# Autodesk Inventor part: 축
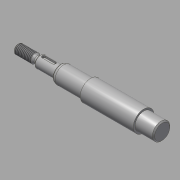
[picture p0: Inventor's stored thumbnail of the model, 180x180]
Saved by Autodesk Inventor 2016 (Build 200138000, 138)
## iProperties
Created: 2015-11
Part Number: 축
Material: 강철, 연강
Document SubType Name: Modeling
Designer: mduedu
Density: 1 g/cm^3
Appearance: 강철
Author: mduedu
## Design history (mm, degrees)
sketch "스케치1"
  geometry: L1 (-86, 0)-(86, 0); L2 (-86, 0)-(-86, 4); L3 (-86, 4)-(-70.732, 4); L4 (-70.732, 4)-(-69, 3); L5 (-69, 3)-(-67, 3); L6 (-67, 3)-(-67, 5); L7 (-67, 5)-(-49, 5); L8 (-49, 5)-(-49, 6.55); L9 (-47.355, 7.5)-(-23, 7.5); L10 (-23, 7.5)-(-23, 9); L11 (0, 0)-(0, 9); L12 (86, 4)-(70.732, 4); L13 (70.732, 4)-(69, 3); L14 (69, 3)-(67, 3); L15 (67, 3)-(67, 5); L16 (67, 5)-(49, 5); L17 (23, 7.5)-(23, 9); L18 (86, 0)-(86, 4); L19 (-23, 9)-(23, 9); L20 (-49, 6.55)-(-47.355, 7.5); L21 (47.355, 7.5)-(23, 7.5); L22 (49, 6.55)-(47.355, 7.5); L23 (49, 5)-(49, 6.55); 1 further point
  constraints: 46 end point, 10 symmetric about line, 6 perpendicular, 5 parallel, 2 midpoint, 1 coincident, 1 horizontal
  dimensions: "d0" = 172 distance of L1.start L1.end (derived); "d1" = 8 diameter of L3 L1; "d2" = 30 deg angle of L4 L5; "d3" = 6 diameter of L5 L1; "d4" = 10 diameter of L7 L1; "d5" = 15 diameter of L9 L1; "d6" = 18 diameter of L19 L1; "d8" = 18 distance of L6.end L7.end; "d9" = 46 distance of L10.end L17.end; "d10" = 2 distance of L4.end L5.end; "d11" = 17 distance from line of L4.end L2; "d16" = 13.1 diameter of L8.end L1; "d17" = 30 deg angle of L20 L9; "d18" = 26 distance between parallel lines of L10 L8
revolve "회전1" sketch "스케치1" stored, may be unused: angle "d12" = 90 deg
chamfer "모따기1" distance "d13" = 1; stored, may be unused: second distance "d14" = 2, angle "d15" = 45 deg
fillet "모깎기1" dims "d19" = 4, "d20" = 0.5
node "작업 평면1"
sketch "스케치2" dims "d23" = 12
  geometry: L1 (-5.5, 1.5)-(3.5, 1.5); L2 (3.5, 1.5)-(3.5, -1.5); L3 (3.5, -1.5)-(-5.5, -1.5); L4 (-5.5, -1.5)-(-5.5, 1.5); L5 (-9, -4)-(-9, 4) reference; 3 further points
  constraints: 8 end point, 2 midpoint, 2 parallel, 2 vertical alignment, 1 horizontal, 1 perpendicular, 4 other
  dimensions: "d21" = 3 distance between parallel lines of L3 L1; "d24" = 2 dimension on L5
extrude "돌출1" cut sketch "스케치2" distance "d25" = 1.8; taper "d26" = 0 deg
feature "스레드1" dims "d27" = 10, "d28" = 0
feature "스레드2" dims "d29" = 10, "d30" = 0
chamfer "모따기2" distance "d31" = 1; stored, may be unused: second distance "d32" = 2, angle "d33" = 45 deg
node "작업 평면2"
sketch "스케치3"
  geometry: C1 r 7.5 at (0, 0) reference; 1 further point
extrude "돌출2" cut sketch "스케치3" stored distance "d36" = 10; taper "d37" = 0 deg
chamfer "모따기3" distance "d38" = 1; stored, may be unused: second distance "d39" = 2, angle "d40" = 45 deg
node "솔리드1"
mirror "대칭1"
node "절단 모서리 투영1"
other parameters: "d35" = 16
